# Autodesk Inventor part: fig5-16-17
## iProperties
Created: 2004-05
Part Number: fig5-16-17
Document SubType Name: Modeling
Designer: CADCIM Technologies
Manufacturer: Standard
Standards Organization: Custom
Density: 1 g/cm^3
Author: CADCIM Technologies
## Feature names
1. Extrusion1
2. Extrusion2
3. Fillet1
